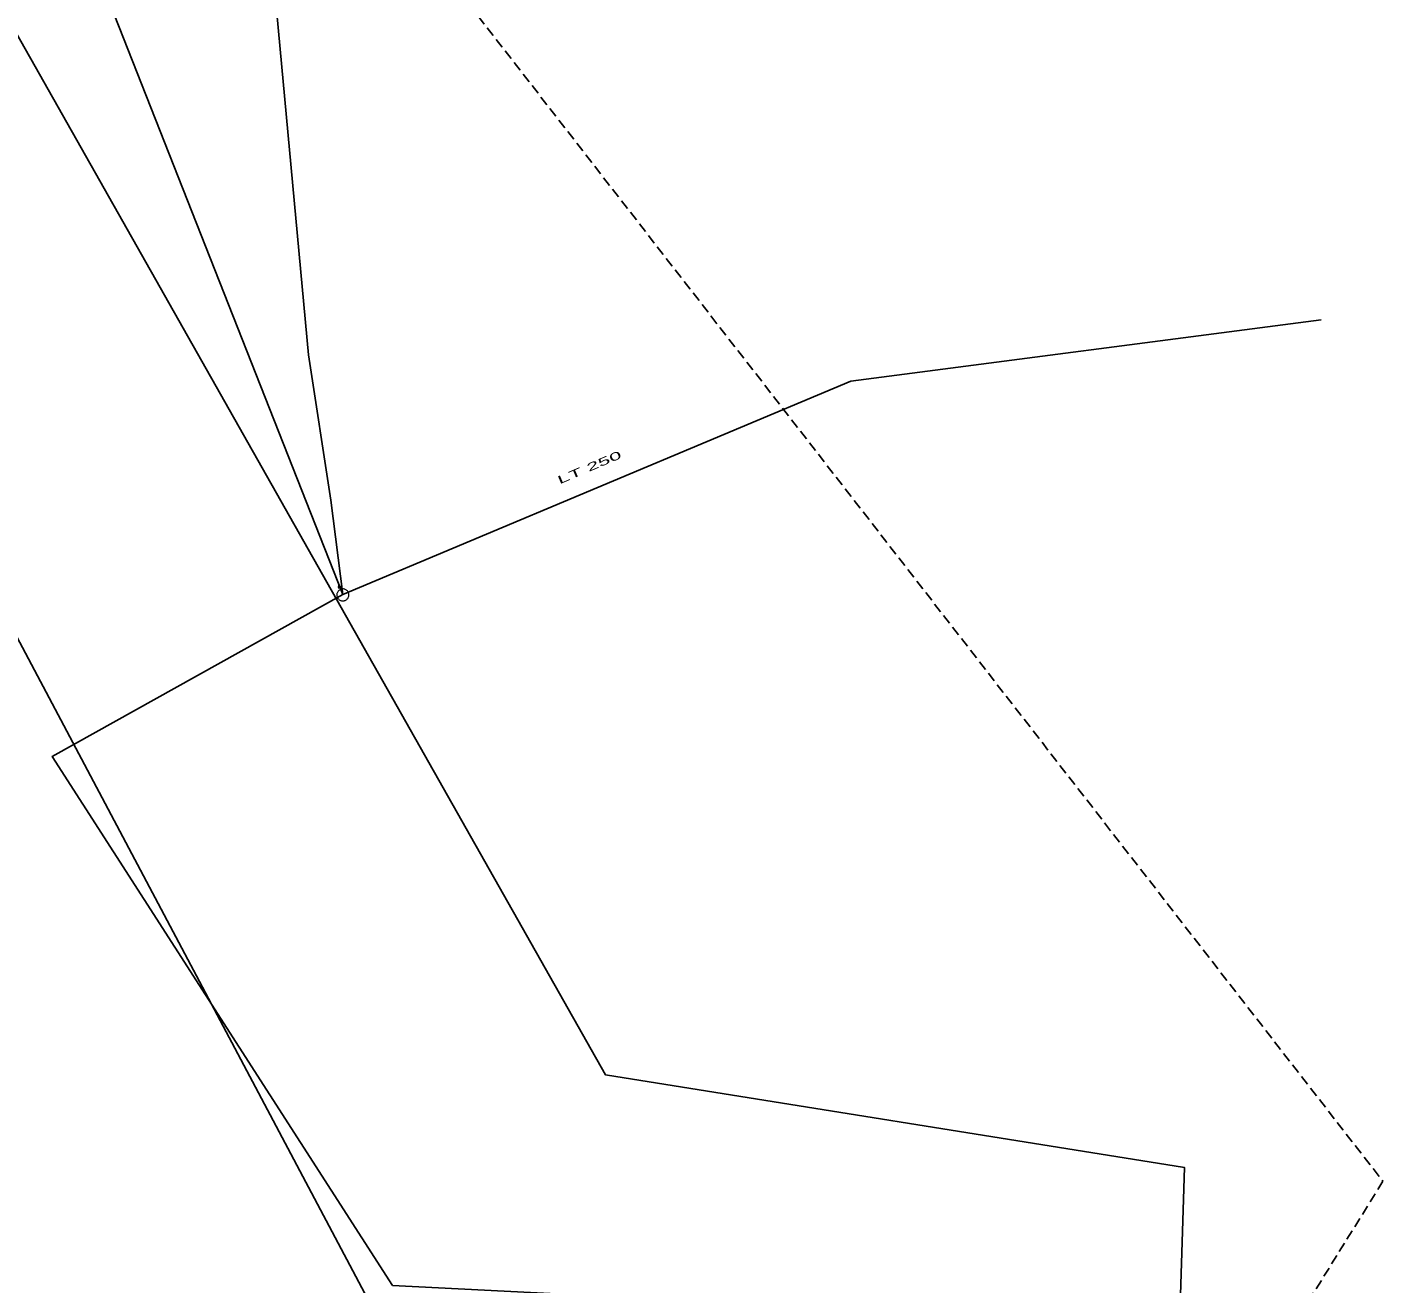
# Model space of a CAD drawing. Extents: x -687593 to -687108, y -975254 to -974717.
# Drawn here: x -687221.2 to -687108.3, y -975149.3 to -975044.6 of the extents above; entities that cross this region are included whole.
import ezdxf
from ezdxf.enums import TextEntityAlignment as Align

# ---------------------------------------------------------------- set-up
doc = ezdxf.new("R2010")
doc.units = 0
doc.header["$LTSCALE"] = 0.27
doc.linetypes.add('MEDIUM_DASHED', pattern=[4.5, 3, -1.5])
for name, color, linetype, lineweight in [('1', 7, 'Continuous', 25), ('17', 7, 'Continuous', 25), ('23', 7, 'Continuous', 13), ('63', 7, 'MEDIUM_DASHED', 25)]:
    doc.layers.add(name, color=color, linetype=linetype, lineweight=lineweight)

msp = doc.modelspace()

# ---------------------------------------------------------------- linework, layer by layer
at = {"layer": '1'}
msp.add_lwpolyline([(-687190.553, -975166.941), (-687164.86, -975177.861), (-687155.924, -975158.837), (-687125.348, -975155.541), (-687124.826, -975139.621), (-687173.065, -975131.89), (-687231.828, -975028.025), (-687222.959, -975015.464), (-687237.898, -975004.026), (-687247.4, -975009.654), (-687276.892, -974983.781), (-687453.606, -974886.044), (-687460.232, -974860.45), (-687474.874, -974858.564), (-687482.889, -974882.272), (-687502.421, -974882.802), (-687499.452, -974907.164), (-687464.42, -974904.824), (-687331.319, -974973.728), (-687252.566, -975037.916), (-687192.379, -975151.48)], close=True, dxfattribs=at)
at = {"layer": '17'}
for points in [[(-687294.34, -974977.541), (-687279.655, -974985.888), (-687216.263, -975037.78), (-687194.919, -975091.897)], [(-687194.919, -975091.897), (-687195.92, -975084.05), (-687197.78, -975071.93), (-687204.501, -974999.426), (-687192.463, -974997.971), (-687180.94, -974996.89)], [(-687194.919, -975091.897), (-687152.638, -975074.125), (-687113.459, -975069.027)], [(-687194.919, -975091.897), (-687219.132, -975105.374), (-687190.795, -975149.44), (-687165.627, -975150.721), (-687169.598, -975253.985)]]:
    msp.add_lwpolyline(points, dxfattribs=at)
at = {"layer": '23'}
msp.add_line((-687195.09, -975091.266), (-687195.271, -975091.342), dxfattribs=at)
for points in [[(-687195.233, -975091.432), (-687195.291, -975091.294), (-687195.258, -975091.117), (-687195.11, -975091.218), (-687195.053, -975091.356)], [(-687194.472, -975091.728), (-687194.495, -975091.68), (-687194.524, -975091.636), (-687194.557, -975091.596), (-687194.593, -975091.558), (-687194.633, -975091.525), (-687194.678, -975091.496), (-687194.724, -975091.472), (-687194.772, -975091.453), (-687194.822, -975091.439), (-687194.874, -975091.43), (-687194.926, -975091.426), (-687194.979, -975091.429), (-687195.031, -975091.436), (-687195.08, -975091.45), (-687195.129, -975091.467), (-687195.178, -975091.492), (-687195.221, -975091.519), (-687195.263, -975091.553), (-687195.299, -975091.587), (-687195.333, -975091.628), (-687195.362, -975091.673), (-687195.386, -975091.719), (-687195.405, -975091.769), (-687195.42, -975091.818), (-687195.428, -975091.869), (-687195.43, -975091.922), (-687195.428, -975091.974), (-687195.421, -975092.026), (-687195.407, -975092.076), (-687195.39, -975092.125), (-687195.367, -975092.172), (-687195.338, -975092.217), (-687195.306, -975092.258), (-687195.269, -975092.295), (-687195.229, -975092.327), (-687195.185, -975092.356), (-687195.139, -975092.381), (-687195.089, -975092.401), (-687195.039, -975092.414)], [(-687195.263, -975091.553), (-687195.299, -975091.587), (-687195.333, -975091.628), (-687195.362, -975091.673), (-687195.386, -975091.719), (-687195.405, -975091.769), (-687195.42, -975091.818), (-687195.428, -975091.869), (-687195.43, -975091.922), (-687195.428, -975091.974), (-687195.421, -975092.026), (-687195.407, -975092.076), (-687195.39, -975092.125), (-687195.367, -975092.172), (-687195.338, -975092.217), (-687195.306, -975092.258), (-687195.269, -975092.295), (-687195.229, -975092.327), (-687195.185, -975092.356), (-687195.139, -975092.381), (-687195.089, -975092.401), (-687195.039, -975092.414), (-687194.989, -975092.423), (-687194.936, -975092.426), (-687194.884, -975092.425), (-687194.831, -975092.416), (-687194.782, -975092.403), (-687194.733, -975092.385), (-687194.686, -975092.361), (-687194.641, -975092.334), (-687194.6, -975092.301), (-687194.563, -975092.264), (-687194.529, -975092.224), (-687194.5, -975092.181), (-687194.477, -975092.133), (-687194.457, -975092.086), (-687194.443, -975092.036), (-687194.434, -975091.983), (-687194.431, -975091.931), (-687194.434, -975091.879)], [(-687195.039, -975092.414), (-687194.989, -975092.423), (-687194.936, -975092.426), (-687194.884, -975092.425), (-687194.831, -975092.416), (-687194.782, -975092.403), (-687194.733, -975092.385), (-687194.686, -975092.361), (-687194.641, -975092.334), (-687194.6, -975092.301), (-687194.563, -975092.264), (-687194.529, -975092.224), (-687194.5, -975092.181), (-687194.477, -975092.133), (-687194.457, -975092.086), (-687194.443, -975092.036), (-687194.434, -975091.983), (-687194.431, -975091.931), (-687194.434, -975091.879), (-687194.442, -975091.827), (-687194.455, -975091.777), (-687194.472, -975091.728), (-687194.495, -975091.68), (-687194.524, -975091.636), (-687194.557, -975091.596), (-687194.593, -975091.558), (-687194.633, -975091.525), (-687194.678, -975091.496), (-687194.724, -975091.472), (-687194.772, -975091.453), (-687194.822, -975091.439), (-687194.874, -975091.43), (-687194.926, -975091.426), (-687194.979, -975091.429), (-687195.031, -975091.436), (-687195.08, -975091.45), (-687195.129, -975091.467), (-687195.178, -975091.492), (-687195.221, -975091.519), (-687195.263, -975091.553)], [(-687194.434, -975091.879), (-687194.442, -975091.827), (-687194.455, -975091.777), (-687194.472, -975091.728)]]:
    msp.add_lwpolyline(points, dxfattribs=at)
at = {"layer": '63'}
msp.add_lwpolyline([(-687526.998, -974914.677), (-687484.572, -974843.781), (-687484.572, -974843.781), (-687425.956, -974881.183), (-687425.956, -974881.183), (-687214.941, -975003.438), (-687214.941, -975003.438), (-687108.316, -975140.766), (-687108.316, -975140.766), (-687138.461, -975189.333), (-687138.461, -975189.333), (-687208.242, -975184.867), (-687208.242, -975184.867), (-687273.556, -975040.84), (-687273.556, -975040.84), (-687454.985, -974924.168), (-687454.985, -974924.168)], close=True, dxfattribs=at)

# ---------------------------------------------------------------- texts
at = {"layer": '1', "width": 2.05}
msp.add_text('LT 250', height=0.6667, rotation=23, dxfattribs=at).set_placement((-687174.2692, -975081.6084), align=Align.CENTER)
msp.add_text('LT 250', height=0.6667, rotation=23, dxfattribs=at).set_placement((-687174.2692, -975081.6084), align=Align.CENTER)
msp.add_text('LT 250', height=0.6667, rotation=23, dxfattribs=at).set_placement((-687174.2692, -975081.6084), align=Align.CENTER)
msp.add_text('LT 250', height=0.6667, rotation=23, dxfattribs=at).set_placement((-687174.2692, -975081.6084), align=Align.CENTER)
msp.add_text('LT 250', height=0.6667, rotation=23, dxfattribs=at).set_placement((-687174.2692, -975081.6084), align=Align.CENTER)

doc.saveas('drawing.dxf')
